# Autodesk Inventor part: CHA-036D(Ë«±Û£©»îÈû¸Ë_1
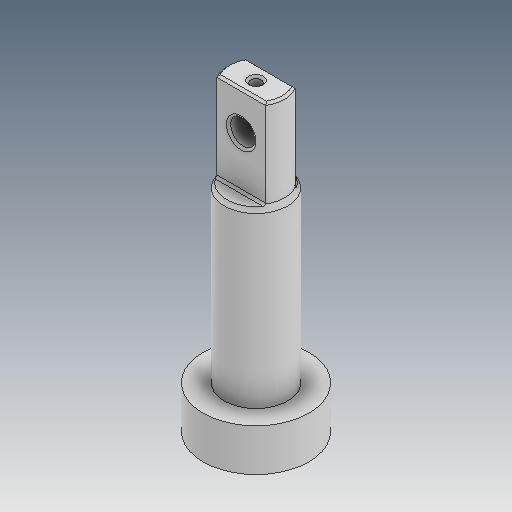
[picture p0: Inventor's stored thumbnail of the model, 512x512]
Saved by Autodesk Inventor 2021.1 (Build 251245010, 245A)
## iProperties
Created: 2019-12
Part Number: CHA-036D(Ë«±Û£©»îÈû¸Ë_1
Material: Ogólny
Document SubType Name: Modeling
Designer: user
Density: 1 g/cm^3
Appearance: Domyślna
Author: user
Revision Number: ÈÎºÎ
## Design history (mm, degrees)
feature "ÊäÈë1"
node "Bryła1"
